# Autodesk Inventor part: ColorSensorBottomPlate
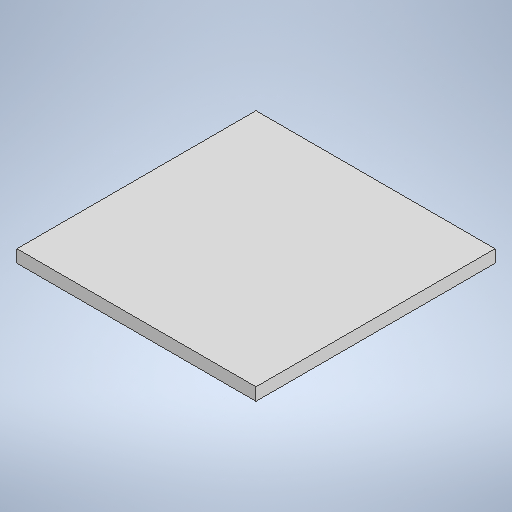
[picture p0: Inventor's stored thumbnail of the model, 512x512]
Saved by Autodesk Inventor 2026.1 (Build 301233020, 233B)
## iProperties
Created: 2026-11
Part Number: ColorSensorBottomPlate
Material: Generic
Document SubType Name: Modeling
Designer: hp
Density: 1 g/cm^3
Appearance: Default
Author: hp
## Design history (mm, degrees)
sketch "Sketch1"
  geometry: L1 (-32.5, 32.5)-(32.5, 32.5); L2 (32.5, 32.5)-(32.5, -32.5); L3 (32.5, -32.5)-(-32.5, -32.5); L4 (-32.5, -32.5)-(-32.5, 32.5); L5 (-32.5, 32.5)-(32.5, -32.5); L6 (32.5, 32.5)-(-32.5, -32.5); L7 (47.5, -47.5)-(47.5, 47.5); L8 (47.5, 47.5)-(-47.5, 47.5); L9 (-47.5, 47.5)-(-47.5, -47.5); L10 (-47.5, -47.5)-(47.5, -47.5); 1 further point
  constraints: 20 end point, 4 parallel, 2 midpoint, 2 perpendicular, 1 horizontal, 3 other
  dimensions: "d0" = 65 distance of L2.end L3.end; "d1" = 65 distance of L1.end L2.end; "d2" = 15 distance between parallel lines of L2 L7
extrude "Extrusion1" new body sketch "Sketch1" distance "d3" = 5; taper "d4" = 0 deg
body "Solid1"
